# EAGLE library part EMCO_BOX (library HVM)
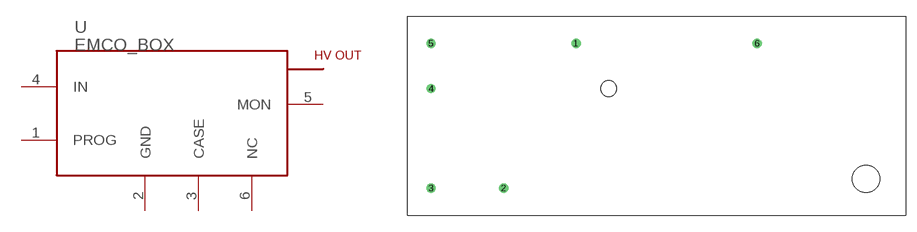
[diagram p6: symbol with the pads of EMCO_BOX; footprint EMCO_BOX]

Designator prefix U

## EMCO_BOX  [EMCO_BOX]
1  PROG  pas
2  GND  pas
3  CASE  pas
4  IN  pas
5  MON  pas
6  NC  nc

## Footprint EMCO_BOX (pad centres in mm)
drill 0.813 round: 1 23.622,24.13; 2 13.462,3.81; 3 3.302,3.81; 4 3.302,17.78; 5 3.302,24.13; 6 49.022,24.13
hole 3.81 at 64.262,5.08
hole 2.184 at 28.194,17.78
